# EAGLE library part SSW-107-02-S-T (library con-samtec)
THROUGH-HOLE .025" SQ POST SOCKET Source: Samtec SSW.pdf
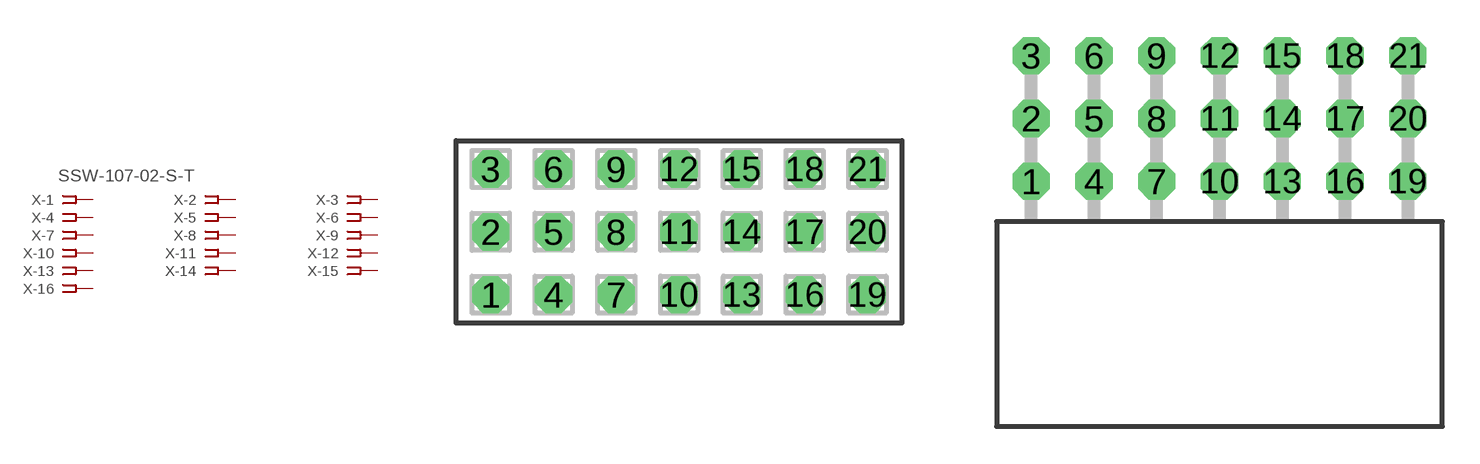
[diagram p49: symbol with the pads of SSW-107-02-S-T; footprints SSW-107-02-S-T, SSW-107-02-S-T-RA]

Designator prefix X; gates -1=FPINV -2=FPIN -3=FPIN -4=FPIN -5=FPIN -6=FPIN -7=FPIN -8=FPIN -9=FPIN -10=FPIN -11=FPIN -12=FPIN -13=FPIN -14=FPIN -15=FPIN -16=FPIN -17=FPIN -18=FPIN -19=FPIN -20=FPIN -21=FPIN

## SSW-107-02-S-T (MPN: SSW-107-02-S-T; OC_FARNELL: unknown; OC_NEWARK: 82P3888)  [SSW-107-02-S-T]
1  -1:1  pas
2  -2:1  pas
3  -3:1  pas
4  -4:1  pas
5  -5:1  pas
6  -6:1  pas
7  -7:1  pas
8  -8:1  pas
9  -9:1  pas
10  -10:1  pas
11  -11:1  pas
12  -12:1  pas
13  -13:1  pas
14  -14:1  pas
15  -15:1  pas
16  -16:1  pas
17  -17:1  pas
18  -18:1  pas
19  -19:1  pas
20  -20:1  pas
21  -21:1  pas

## SSW-107-02-S-TRA (MPN: SSW-107-02-S-T-RA; OC_FARNELL: unknown; OC_NEWARK: 82P3889)  [SSW-107-02-S-T-RA]
Pads as for SSW-107-02-S-T

## Footprint SSW-107-02-S-T (pad centres in mm)
THROUGH-HOLE .025" SQ POST SOCKET Source: Samtec SSW.pdf
drill 1 pad 1.5 octagon: 1 -7.62,-2.54; 2 -7.62,0; 3 -7.62,2.54; 4 -5.08,-2.54; 5 -5.08,0; 6 -5.08,2.54; 7 -2.54,-2.54; 8 -2.54,0; 9 -2.54,2.54; 10 0,-2.54; 11 0,0; 12 0,2.54; 13 2.54,-2.54; 14 2.54,0; 15 2.54,2.54; 16 5.08,-2.54; 17 5.08,0; 18 5.08,2.54; 19 7.62,-2.54; 20 7.62,0; 21 7.62,2.54

## Footprint SSW-107-02-S-T-RA (pad centres in mm)
THROUGH-HOLE .025" SQ POST SOCKET Source: Samtec SSW.pdf
drill 1 pad 1.5 octagon: 1 -7.62,1.524; 2 -7.62,4.064; 3 -7.62,6.604; 4 -5.08,1.524; 5 -5.08,4.064; 6 -5.08,6.604; 7 -2.54,1.524; 8 -2.54,4.064; 9 -2.54,6.604; 10 0,1.524; 11 0,4.064; 12 0,6.604; 13 2.54,1.524; 14 2.54,4.064; 15 2.54,6.604; 16 5.08,1.524; 17 5.08,4.064; 18 5.08,6.604; 19 7.62,1.524; 20 7.62,4.064; 21 7.62,6.604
